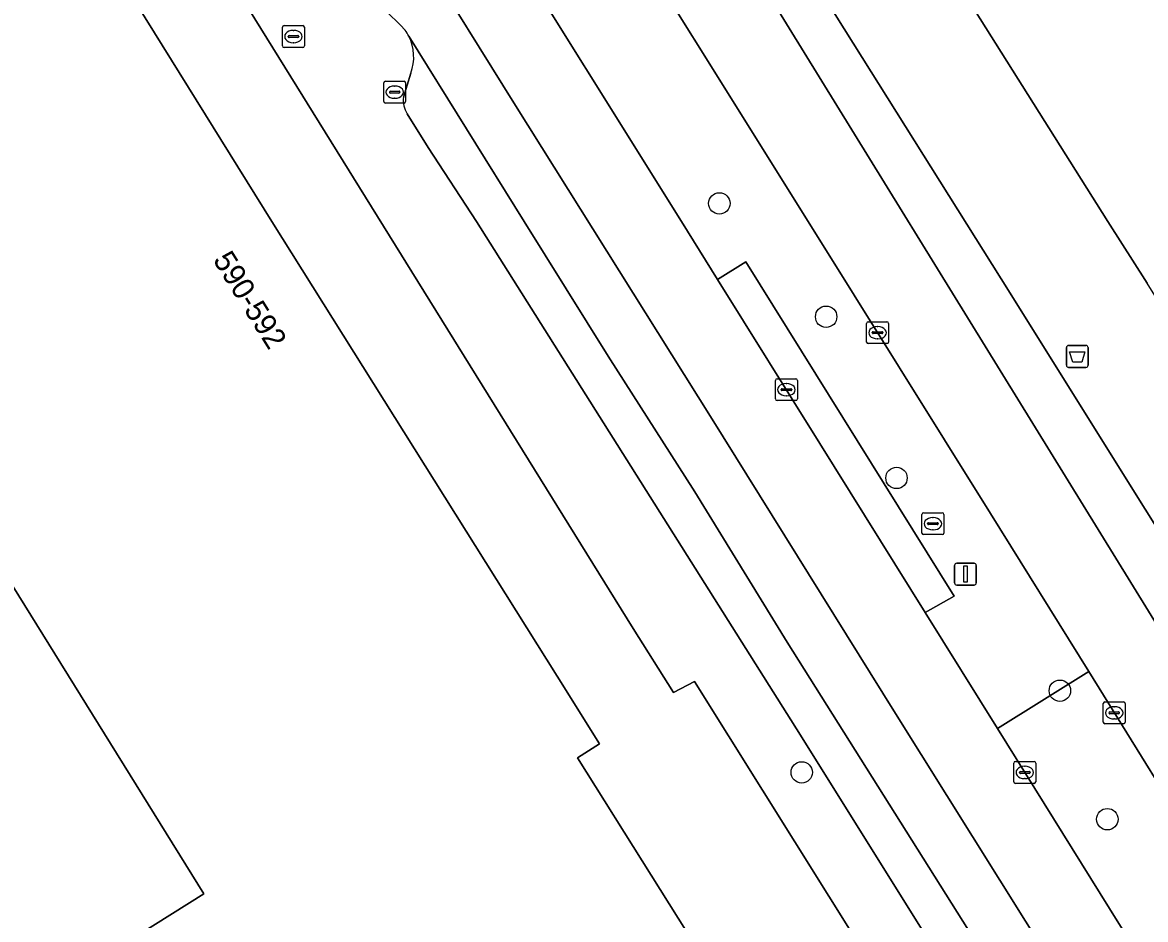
# Model space of a CAD drawing. Extents: x 158455 to 159797, y 387218 to 388672.
# Drawn here: x 158762.6 to 158813.9, y 387968.1 to 388009.1 of the extents above; entities that cross this region are included whole.
import ezdxf

# ---------------------------------------------------------------- set-up
doc = ezdxf.new("R2010")
doc.units = 0
for name, color, linetype in [('IMGEO_Afvalbak', 7, 'Continuous'), ('IMGEO_Berm_groen', 7, 'Continuous'), ('IMGEO_Boom', 7, 'Continuous'), ('IMGEO_Brandkraan', 7, 'Continuous'), ('IMGEO_Erf', 7, 'Continuous'), ('IMGEO_Kolk', 7, 'Continuous'), ('IMGEO_Lichtmast', 7, 'Continuous'), ('IMGEO_Pand', 7, 'Continuous'), ('IMGEO_Pand_nummerreeks', 7, 'Continuous'), ('IMGEO_Parkeervlak_open', 7, 'Continuous'), ('IMGEO_Rijbaan_lokaal_gesloten', 7, 'Continuous'), ('IMGEO_Rioolput', 7, 'Continuous'), ('IMGEO_Voetpad_open', 7, 'Continuous')]:
    doc.layers.add(name, color=color, linetype=linetype)

msp = doc.modelspace()

# ---------------------------------------------------------------- linework, layer by layer
at = {"layer": 'IMGEO_Afvalbak'}
for p, q in [((158810.264, 387993.432), (158810.264, 387994.232)), ((158810.264, 387994.232), (158810.264, 387993.432)), ((158810.364, 387994.332), (158811.154, 387994.332)), ((158811.154, 387994.332), (158810.364, 387994.332)), ((158811.254, 387994.232), (158811.254, 387993.432)), ((158811.254, 387993.432), (158811.254, 387994.232)), ((158811.154, 387993.332), (158810.364, 387993.332)), ((158810.364, 387993.332), (158811.154, 387993.332))]:
    msp.add_line(p, q, dxfattribs=at)
msp.add_lwpolyline([(158810.407, 387994.046), (158811.111, 387994.046), (158810.962, 387993.576), (158810.556, 387993.576), (158810.407, 387994.046)], dxfattribs=at)
for centre, start, end in [((158810.364, 387994.232), 90, 180), ((158810.364, 387994.232), 90, 180), ((158811.154, 387994.232), 0, 90), ((158811.154, 387994.232), 360, 90), ((158810.364, 387993.432), 180, 270), ((158810.364, 387993.432), 180, 270), ((158811.154, 387993.432), 270, 0), ((158811.154, 387993.432), 270, 0)]:
    msp.add_arc(centre, 0.1, start, end, dxfattribs=at)
at = {"layer": 'IMGEO_Berm_groen'}
for points in [[(158798.463, 388000), (158787.973, 388016.798), (158783.864, 388014.122), (158792.673, 388000), (158794.325, 387997.351), (158795.612, 387998.155), (158805.13, 387982.878), (158803.816, 387982.123), (158807.11, 387976.831), (158811.283, 387979.426), (158806.797, 387986.65)], [(158795.612, 387998.155), (158794.325, 387997.351), (158799.003, 387989.853), (158803.816, 387982.123), (158805.13, 387982.878)], [(158816.975, 387970.262), (158811.283, 387979.426), (158807.11, 387976.831), (158812.237, 387968.597), (158824.322, 387949.219), (158837.096, 387928.793), (158852.17, 387904.676), (158856.298, 387907.238), (158851.263, 387915.352), (158842.383, 387929.569)]]:
    msp.add_lwpolyline(points, close=True, dxfattribs=at)
at = {"layer": 'IMGEO_Boom'}
for centre in [(158794.406, 388000.822), (158799.286, 387995.643), (158802.501, 387988.278), (158809.965, 387978.555), (158798.171, 387974.821), (158812.134, 387972.684)]:
    msp.add_circle(centre, 0.489, dxfattribs=at)
at = {"layer": 'IMGEO_Brandkraan'}
for p, q in [((158774.443, 388008.023), (158774.443, 388008.875)), ((158774.518, 388008.949), (158775.37, 388008.949)), ((158774.931, 388008.729), (158774.956, 388008.729)), ((158775.444, 388008.875), (158775.444, 388008.023)), ((158774.702, 388008.443), (158774.702, 388008.455)), ((158775.14, 388008.406), (158774.742, 388008.406)), ((158774.745, 388008.492), (158775.143, 388008.492)), ((158775.186, 388008.455), (158775.186, 388008.443)), ((158775.37, 388007.949), (158774.518, 388007.949)), ((158774.954, 388008.169), (158774.929, 388008.169))]:
    msp.add_line(p, q, dxfattribs=at)
for points in [[(158774.443, 388008.023), (158774.443, 388008.875)], [(158774.518, 388008.949), (158775.37, 388008.949)], [(158775.444, 388008.875), (158775.444, 388008.023)], [(158775.37, 388007.949), (158774.518, 388007.949)]]:
    msp.add_lwpolyline(points, dxfattribs=at)
for centre, radius, start, end in [((158774.52, 388008.873), 0.0765, 91.552, 178.448), ((158774.52, 388008.873), 0.0765, 91.552, 178.448), ((158775.368, 388008.873), 0.0765, 1.552, 88.448), ((158775.368, 388008.873), 0.0765, 1.552, 88.448), ((158774.742, 388008.452), 0.0403, 85.8775, 175.7526), ((158774.739, 388008.442), 0.0366, 178.938, 274.7102), ((158775.143, 388008.449), 0.043, 264.8664, 352.4533), ((158775.147, 388008.454), 0.0386, 1.7309, 96.639), ((158774.52, 388008.025), 0.0765, 181.552, 268.448), ((158774.52, 388008.025), 0.0765, 181.552, 268.448), ((158775.368, 388008.025), 0.0765, 271.552, 358.448), ((158775.368, 388008.025), 0.0765, 271.552, 358.448)]:
    msp.add_arc(centre, radius, start, end, dxfattribs=at)
for centre, major_axis, ratio, start_param, end_param in [((158774.93, 388008.449), (-0.387, 0.002), 0.722429, 4.712389, 7.853982), ((158774.955, 388008.449), (-0.39, 0.002), 0.717154, 1.570796, 4.712389)]:
    msp.add_ellipse(centre, major_axis=major_axis, ratio=ratio, start_param=start_param, end_param=end_param, dxfattribs=at)
at = {"layer": 'IMGEO_Erf'}
for points in [[(158854.735, 387880.753), (158793.275, 387978.973), (158792.305, 387978.478), (158790.47, 387981.392), (158753.29, 388041.304)], [(158815.405, 388018.358), (158811.188, 388015.723), (158809.906, 388017.776), (158811.078, 388018.509), (158814.139, 388020.423), (158810.509, 388026.233), (158807.435, 388024.334), (158798.408, 388018.757), (158801.869, 388013.247), (158804.148, 388012.735), (158812.156, 388000), (158813.957, 387997.174)], [(158758.286, 388025.218), (158763.813, 388016.323), (158762.622, 388015.583), (158763.942, 388013.46), (158765.132, 388014.2), (158773.954, 388000), (158786.995, 387979.213), (158788.935, 387976.121), (158787.923, 387975.486), (158794.654, 387964.764)], [(158749.281, 387955.743), (158770.844, 387969.279), (158753.021, 387997.953)]]:
    msp.add_lwpolyline(points, dxfattribs=at)
at = {"layer": 'IMGEO_Kolk'}
for p, q in [((158779.07, 388005.481), (158779.07, 388006.333)), ((158779.145, 388006.407), (158779.997, 388006.407)), ((158779.558, 388006.187), (158779.583, 388006.187)), ((158780.071, 388006.333), (158780.071, 388005.481)), ((158779.329, 388005.901), (158779.329, 388005.913)), ((158779.767, 388005.864), (158779.369, 388005.864)), ((158779.372, 388005.95), (158779.77, 388005.95)), ((158779.813, 388005.913), (158779.813, 388005.901)), ((158779.997, 388005.407), (158779.145, 388005.407)), ((158779.581, 388005.627), (158779.556, 388005.627)), ((158801.21, 387995.415), (158802.062, 387995.415)), ((158801.135, 387994.489), (158801.135, 387995.341)), ((158801.394, 387994.909), (158801.394, 387994.921)), ((158801.832, 387994.872), (158801.434, 387994.872)), ((158801.437, 387994.958), (158801.835, 387994.958)), ((158801.623, 387995.195), (158801.648, 387995.195)), ((158801.878, 387994.921), (158801.878, 387994.909)), ((158802.136, 387995.341), (158802.136, 387994.489)), ((158802.062, 387994.415), (158801.21, 387994.415)), ((158801.646, 387994.635), (158801.621, 387994.635)), ((158796.969, 387991.886), (158796.969, 387992.738)), ((158797.044, 387992.812), (158797.896, 387992.812)), ((158797.228, 387992.306), (158797.228, 387992.318)), ((158797.271, 387992.355), (158797.669, 387992.355)), ((158797.457, 387992.592), (158797.482, 387992.592)), ((158797.712, 387992.318), (158797.712, 387992.306)), ((158797.97, 387992.738), (158797.97, 387991.886)), ((158797.896, 387991.812), (158797.044, 387991.812)), ((158797.666, 387992.269), (158797.268, 387992.269)), ((158797.48, 387992.032), (158797.455, 387992.032)), ((158811.951, 387977.117), (158811.951, 387977.969)), ((158812.026, 387978.043), (158812.878, 387978.043)), ((158812.952, 387977.969), (158812.952, 387977.117)), ((158812.21, 387977.537), (158812.21, 387977.549)), ((158812.648, 387977.5), (158812.25, 387977.5)), ((158812.253, 387977.586), (158812.651, 387977.586)), ((158812.439, 387977.823), (158812.464, 387977.823)), ((158812.694, 387977.549), (158812.694, 387977.537)), ((158812.878, 387977.043), (158812.026, 387977.043)), ((158812.462, 387977.263), (158812.437, 387977.263)), ((158807.862, 387974.394), (158807.862, 387975.246)), ((158807.937, 387975.32), (158808.789, 387975.32)), ((158808.164, 387974.863), (158808.562, 387974.863)), ((158808.35, 387975.1), (158808.375, 387975.1)), ((158808.863, 387975.246), (158808.863, 387974.394)), ((158808.121, 387974.814), (158808.121, 387974.826)), ((158808.559, 387974.777), (158808.161, 387974.777)), ((158808.373, 387974.54), (158808.348, 387974.54)), ((158808.605, 387974.826), (158808.605, 387974.814)), ((158808.789, 387974.32), (158807.937, 387974.32))]:
    msp.add_line(p, q, dxfattribs=at)
for points in [[(158779.07, 388005.481), (158779.07, 388006.333)], [(158779.145, 388006.407), (158779.997, 388006.407)], [(158780.071, 388006.333), (158780.071, 388005.481)], [(158779.997, 388005.407), (158779.145, 388005.407)], [(158801.21, 387995.415), (158802.062, 387995.415)], [(158801.135, 387994.489), (158801.135, 387995.341)], [(158802.136, 387995.341), (158802.136, 387994.489)], [(158802.062, 387994.415), (158801.21, 387994.415)], [(158796.969, 387991.886), (158796.969, 387992.738)], [(158797.044, 387992.812), (158797.896, 387992.812)], [(158797.97, 387992.738), (158797.97, 387991.886)], [(158797.896, 387991.812), (158797.044, 387991.812)], [(158811.951, 387977.117), (158811.951, 387977.969)], [(158812.026, 387978.043), (158812.878, 387978.043)], [(158812.952, 387977.969), (158812.952, 387977.117)], [(158812.878, 387977.043), (158812.026, 387977.043)], [(158807.862, 387974.394), (158807.862, 387975.246)], [(158807.937, 387975.32), (158808.789, 387975.32)], [(158808.863, 387975.246), (158808.863, 387974.394)], [(158808.789, 387974.32), (158807.937, 387974.32)]]:
    msp.add_lwpolyline(points, dxfattribs=at)
for centre, radius, start, end in [((158779.147, 388006.331), 0.0765, 91.552, 178.448), ((158779.147, 388006.331), 0.0765, 91.552, 178.448), ((158779.995, 388006.331), 0.0765, 1.552, 88.448), ((158779.995, 388006.331), 0.0765, 1.552, 88.448), ((158779.369, 388005.91), 0.0403, 85.8775, 175.7526), ((158779.366, 388005.9), 0.0366, 178.938, 274.7102), ((158779.77, 388005.907), 0.043, 264.8664, 352.4533), ((158779.774, 388005.912), 0.0386, 1.7309, 96.639), ((158779.147, 388005.483), 0.0765, 181.552, 268.448), ((158779.147, 388005.483), 0.0765, 181.552, 268.448), ((158779.995, 388005.483), 0.0765, 271.552, 358.448), ((158779.995, 388005.483), 0.0765, 271.552, 358.448), ((158801.212, 387995.339), 0.0765, 91.552, 178.448), ((158801.212, 387995.339), 0.0765, 91.552, 178.448), ((158802.06, 387995.339), 0.0765, 1.552, 88.448), ((158802.06, 387995.339), 0.0765, 1.552, 88.448), ((158801.434, 387994.918), 0.0403, 85.8775, 175.7526), ((158801.431, 387994.908), 0.0366, 178.938, 274.7102), ((158801.835, 387994.915), 0.043, 264.8664, 352.4533), ((158801.839, 387994.92), 0.0386, 1.7309, 96.639), ((158801.212, 387994.491), 0.0765, 181.552, 268.448), ((158801.212, 387994.491), 0.0765, 181.552, 268.448), ((158802.06, 387994.491), 0.0765, 271.552, 358.448), ((158802.06, 387994.491), 0.0765, 271.552, 358.448), ((158797.046, 387992.736), 0.0765, 91.552, 178.448), ((158797.046, 387992.736), 0.0765, 91.552, 178.448), ((158797.268, 387992.315), 0.0403, 85.8775, 175.7526), ((158797.265, 387992.305), 0.0366, 178.938, 274.7102), ((158797.669, 387992.312), 0.043, 264.8664, 352.4533), ((158797.673, 387992.317), 0.0386, 1.7309, 96.639), ((158797.894, 387992.736), 0.0765, 1.552, 88.448), ((158797.894, 387992.736), 0.0765, 1.552, 88.448), ((158797.046, 387991.888), 0.0765, 181.552, 268.448), ((158797.046, 387991.888), 0.0765, 181.552, 268.448), ((158797.894, 387991.888), 0.0765, 271.552, 358.448), ((158797.894, 387991.888), 0.0765, 271.552, 358.448), ((158812.028, 387977.967), 0.0765, 91.552, 178.448), ((158812.028, 387977.967), 0.0765, 91.552, 178.448), ((158812.876, 387977.967), 0.0765, 1.552, 88.448), ((158812.876, 387977.967), 0.0765, 1.552, 88.448), ((158812.25, 387977.546), 0.0403, 85.8775, 175.7526), ((158812.247, 387977.536), 0.0366, 178.938, 274.7102), ((158812.651, 387977.543), 0.043, 264.8664, 352.4533), ((158812.655, 387977.548), 0.0386, 1.7309, 96.639), ((158812.028, 387977.119), 0.0765, 181.552, 268.448), ((158812.028, 387977.119), 0.0765, 181.552, 268.448), ((158812.876, 387977.119), 0.0765, 271.552, 358.448), ((158812.876, 387977.119), 0.0765, 271.552, 358.448), ((158807.939, 387975.244), 0.0765, 91.552, 178.448), ((158807.939, 387975.244), 0.0765, 91.552, 178.448), ((158808.161, 387974.823), 0.0403, 85.8775, 175.7526), ((158808.566, 387974.825), 0.0386, 1.7309, 96.639), ((158808.787, 387975.244), 0.0765, 1.552, 88.448), ((158808.787, 387975.244), 0.0765, 1.552, 88.448), ((158807.939, 387974.396), 0.0765, 181.552, 268.448), ((158807.939, 387974.396), 0.0765, 181.552, 268.448), ((158808.158, 387974.813), 0.0366, 178.938, 274.7102), ((158808.562, 387974.82), 0.043, 264.8664, 352.4533), ((158808.787, 387974.396), 0.0765, 271.552, 358.448), ((158808.787, 387974.396), 0.0765, 271.552, 358.448)]:
    msp.add_arc(centre, radius, start, end, dxfattribs=at)
for centre, major_axis, ratio, start_param, end_param in [((158779.557, 388005.907), (-0.387, 0.002), 0.722429, 4.712389, 7.853982), ((158779.582, 388005.907), (-0.39, 0.002), 0.717154, 1.570796, 4.712389), ((158801.622, 387994.915), (-0.387, 0.002), 0.722429, 4.712389, 7.853982), ((158801.647, 387994.915), (-0.39, 0.002), 0.717154, 1.570796, 4.712389), ((158797.456, 387992.312), (-0.387, 0.002), 0.722429, 4.712389, 7.853982), ((158797.481, 387992.312), (-0.39, 0.002), 0.717154, 1.570796, 4.712389), ((158812.438, 387977.543), (-0.387, 0.002), 0.722429, 4.712389, 7.853982), ((158812.463, 387977.543), (-0.39, 0.002), 0.717154, 1.570796, 4.712389), ((158808.349, 387974.82), (-0.387, 0.002), 0.722429, 4.712389, 7.853982), ((158808.374, 387974.82), (-0.39, 0.002), 0.717154, 1.570796, 4.712389)]:
    msp.add_ellipse(centre, major_axis=major_axis, ratio=ratio, start_param=start_param, end_param=end_param, dxfattribs=at)
at = {"layer": 'IMGEO_Lichtmast'}
for p, q in [((158805.155, 387983.483), (158805.155, 387984.283)), ((158805.155, 387984.283), (158805.155, 387983.483)), ((158805.255, 387984.383), (158806.045, 387984.383)), ((158806.045, 387984.383), (158805.255, 387984.383)), ((158806.145, 387984.283), (158806.145, 387983.483)), ((158806.145, 387983.483), (158806.145, 387984.283)), ((158806.045, 387983.383), (158805.255, 387983.383)), ((158805.255, 387983.383), (158806.045, 387983.383))]:
    msp.add_line(p, q, dxfattribs=at)
msp.add_lwpolyline([(158805.575, 387984.258), (158805.725, 387984.258), (158805.725, 387983.508), (158805.575, 387983.508), (158805.575, 387984.258)], dxfattribs=at)
for centre, start, end in [((158805.255, 387984.283), 90, 180), ((158805.255, 387984.283), 90, 180), ((158806.045, 387984.283), 0, 90), ((158806.045, 387984.283), 360, 90), ((158805.255, 387983.483), 180, 270), ((158805.255, 387983.483), 180, 270), ((158806.045, 387983.483), 270, 0), ((158806.045, 387983.483), 270, 0)]:
    msp.add_arc(centre, 0.1, start, end, dxfattribs=at)
at = {"layer": 'IMGEO_Pand'}
msp.add_lwpolyline([(158758.286, 388025.218), (158746.563, 388017.931), (158757.32, 388000.625), (158756.314, 388000), (158753.021, 387997.953), (158770.844, 387969.279), (158749.281, 387955.743), (158745.046, 387953.084), (158755.718, 387936.084), (158760.153, 387938.869), (158797.52, 387962.365), (158795.624, 387965.373), (158794.654, 387964.764), (158787.923, 387975.486), (158788.935, 387976.121), (158786.995, 387979.213), (158773.954, 388000), (158765.132, 388014.2), (158763.942, 388013.46), (158762.622, 388015.583), (158763.813, 388016.323)], close=True, dxfattribs=at)
at = {"layer": 'IMGEO_Parkeervlak_open'}
for points in [[(158816.677, 387949.935), (158806.829, 387965.972), (158797.5, 387980.78), (158793.285, 387987.639), (158789.331, 387993.838), (158785.494, 388000), (158780.215, 388008.468)], [(158780.31, 388006.783), (158779.974, 388005.686)], [(158780.136, 388004.918), (158781.104, 388003.382), (158783.303, 388000), (158798.109, 387976.516), (158844.522, 387902.25), (158846.16, 387899.629), (158846.848, 387898.516), (158857.012, 387882.068)]]:
    msp.add_lwpolyline(points, dxfattribs=at)
for centre, radius, start, end in [((158778.314, 388007.516), 2.126, 339.8416, 26.6123), ((158781.105, 388005.523), 1.142, 171.8163, 212.0061)]:
    msp.add_arc(centre, radius, start, end, dxfattribs=at)
at = {"layer": 'IMGEO_Rijbaan_lokaal_gesloten'}
for points in [[(158753.852, 388043.019), (158754.038, 388042.762), (158763.975, 388026.751), (158769.433, 388017.98), (158774.688, 388013.388), (158779.204, 388009.58), (158779.842, 388008.974), (158780.048, 388008.741)], [(158871.964, 387889.05), (158834.227, 387949.391), (158792.31, 388017.418), (158777.679, 388039.896)], [(158774.752, 388037.976), (158786.347, 388019.403), (158787.973, 388016.798), (158798.463, 388000), (158806.797, 387986.65), (158811.283, 387979.426), (158816.975, 387970.262), (158842.383, 387929.569), (158851.263, 387915.352), (158856.298, 387907.238), (158856.412, 387907.055), (158857.076, 387905.984), (158857.412, 387905.443), (158858.993, 387902.895), (158866.508, 387890.905)], [(158824.322, 387949.219), (158812.237, 387968.597), (158807.11, 387976.831), (158803.816, 387982.123), (158799.003, 387989.853), (158794.325, 387997.351), (158792.673, 388000), (158783.864, 388014.122), (158783.741, 388014.319), (158782.225, 388016.719), (158770.717, 388035.097), (158765.602, 388032.001), (158765.806, 388031.671), (158773.443, 388019.409), (158774.78, 388017.262), (158774.869, 388017.05), (158778.332, 388014.385), (158779.563, 388013.342), (158780.694, 388012.384), (158785.095, 388005.301), (158793.995, 387991.082), (158802.455, 387977.515), (158810.737, 387964.275)], [(158853.754, 387895.444), (158836.678, 387922.775), (158822.801, 387944.946), (158810.737, 387964.275), (158802.455, 387977.515), (158793.995, 387991.082), (158785.095, 388005.301), (158780.694, 388012.384), (158779.563, 388013.342), (158778.332, 388014.385), (158774.869, 388017.05)], [(158780.215, 388008.468), (158785.494, 388000), (158789.331, 387993.838), (158793.285, 387987.639), (158797.5, 387980.78), (158806.829, 387965.972), (158816.677, 387949.935), (158827.094, 387933.478), (158837.312, 387917.021), (158848.058, 387899.934), (158855.269, 387888.326), (158860.281, 387880.424), (158864.153, 387874.318), (158873.777, 387859.01), (158875.717, 387855.924), (158877.701, 387857.148), (158853.754, 387895.444)]]:
    msp.add_lwpolyline(points, dxfattribs=at)
msp.add_lwpolyline([(158857.71, 387916.557), (158844.256, 387938.083), (158828.405, 387963.308), (158826.242, 387967.003), (158821.291, 387974.98), (158819.155, 387978.39), (158808.574, 387995.299), (158807.699, 387996.716), (158779.748, 388041.252), (158777.679, 388039.896), (158792.31, 388017.418), (158834.227, 387949.391), (158871.964, 387889.05), (158887.922, 387863.502), (158890.244, 387864.932), (158881.497, 387878.849), (158879.01, 387882.568), (158877.715, 387884.504), (158870.764, 387895.592)], close=True, dxfattribs=at)
msp.add_arc((158778.448, 388007.575), 1.98, 26.8196, 36.0905, dxfattribs=at)
at = {"layer": 'IMGEO_Rioolput'}
for p, q in [((158803.74, 387986.687), (158804.592, 387986.687)), ((158803.665, 387985.761), (158803.665, 387986.613)), ((158803.924, 387986.181), (158803.924, 387986.193)), ((158803.967, 387986.23), (158804.365, 387986.23)), ((158804.153, 387986.467), (158804.178, 387986.467)), ((158804.408, 387986.193), (158804.408, 387986.181)), ((158804.666, 387986.613), (158804.666, 387985.761)), ((158804.592, 387985.687), (158803.74, 387985.687)), ((158804.362, 387986.144), (158803.964, 387986.144)), ((158804.176, 387985.907), (158804.151, 387985.907))]:
    msp.add_line(p, q, dxfattribs=at)
for points in [[(158803.74, 387986.687), (158804.592, 387986.687)], [(158803.665, 387985.761), (158803.665, 387986.613)], [(158804.666, 387986.613), (158804.666, 387985.761)], [(158804.592, 387985.687), (158803.74, 387985.687)]]:
    msp.add_lwpolyline(points, dxfattribs=at)
for centre, radius, start, end in [((158803.742, 387986.611), 0.0765, 91.552, 178.448), ((158803.742, 387986.611), 0.0765, 91.552, 178.448), ((158804.59, 387986.611), 0.0765, 1.552, 88.448), ((158804.59, 387986.611), 0.0765, 1.552, 88.448), ((158803.964, 387986.19), 0.0403, 85.8775, 175.7526), ((158803.961, 387986.18), 0.0366, 178.938, 274.7102), ((158804.365, 387986.187), 0.043, 264.8664, 352.4533), ((158804.369, 387986.192), 0.0386, 1.7309, 96.639), ((158803.742, 387985.763), 0.0765, 181.552, 268.448), ((158803.742, 387985.763), 0.0765, 181.552, 268.448), ((158804.59, 387985.763), 0.0765, 271.552, 358.448), ((158804.59, 387985.763), 0.0765, 271.552, 358.448)]:
    msp.add_arc(centre, radius, start, end, dxfattribs=at)
for centre, major_axis, ratio, start_param, end_param in [((158804.152, 387986.187), (-0.387, 0.002), 0.722429, 4.712389, 7.853982), ((158804.177, 387986.187), (-0.39, 0.002), 0.717154, 1.570796, 4.712389)]:
    msp.add_ellipse(centre, major_axis=major_axis, ratio=ratio, start_param=start_param, end_param=end_param, dxfattribs=at)
at = {"layer": 'IMGEO_Voetpad_open'}
for points in [[(158831.334, 387966.514), (158826.221, 387974.793), (158827.359, 387975.532), (158825.428, 387978.622), (158823.292, 387982.041), (158820.433, 387986.616), (158818.2, 387990.263), (158816.22, 387993.495), (158814.961, 387995.567), (158813.957, 387997.174), (158812.156, 388000), (158804.148, 388012.735), (158801.869, 388013.247), (158798.408, 388018.757), (158797.295, 388020.528), (158796.197, 388019.813), (158793.639, 388023.916), (158778.006, 388048.991), (158777.07, 388050.354), (158773.887, 388055.513), (158773.46, 388055.233)], [(158772.646, 388052.678), (158776.275, 388046.877), (158779.748, 388041.252), (158807.699, 387996.716), (158808.574, 387995.299), (158819.155, 387978.39), (158821.291, 387974.98), (158826.242, 387967.003), (158827.473, 387966.317), (158828.388, 387966.155)], [(158750.225, 388044.567), (158751.855, 388042.396), (158752.718, 388041.901), (158753.29, 388041.304), (158790.47, 387981.392), (158792.305, 387978.478), (158793.275, 387978.973), (158854.735, 387880.753), (158857.012, 387882.068), (158846.848, 387898.516)], [(158780.048, 388008.741), (158779.842, 388008.974), (158779.204, 388009.58), (158774.688, 388013.388), (158769.433, 388017.98), (158763.975, 388026.751), (158754.038, 388042.762), (158753.852, 388043.019), (158753.577, 388042.844)], [(158779.974, 388005.686), (158780.31, 388006.783)], [(158846.848, 387898.516), (158846.424, 387898.252), (158844.098, 387901.986), (158844.522, 387902.25), (158798.109, 387976.516), (158783.303, 388000), (158781.104, 388003.382), (158780.136, 388004.918)]]:
    msp.add_lwpolyline(points, dxfattribs=at)
for centre, radius, start, end in [((158778.448, 388007.575), 1.98, 26.8196, 36.0905), ((158778.314, 388007.516), 2.126, 339.8416, 26.6123), ((158781.105, 388005.523), 1.142, 171.8163, 212.0061)]:
    msp.add_arc(centre, radius, start, end, dxfattribs=at)

# ---------------------------------------------------------------- texts
at = {"layer": 'IMGEO_Pand_nummerreeks'}
msp.add_text('590-592', height=1, rotation=302.0008, dxfattribs=at).set_placement((158771.239, 387998.238))

doc.saveas('drawing.dxf')
